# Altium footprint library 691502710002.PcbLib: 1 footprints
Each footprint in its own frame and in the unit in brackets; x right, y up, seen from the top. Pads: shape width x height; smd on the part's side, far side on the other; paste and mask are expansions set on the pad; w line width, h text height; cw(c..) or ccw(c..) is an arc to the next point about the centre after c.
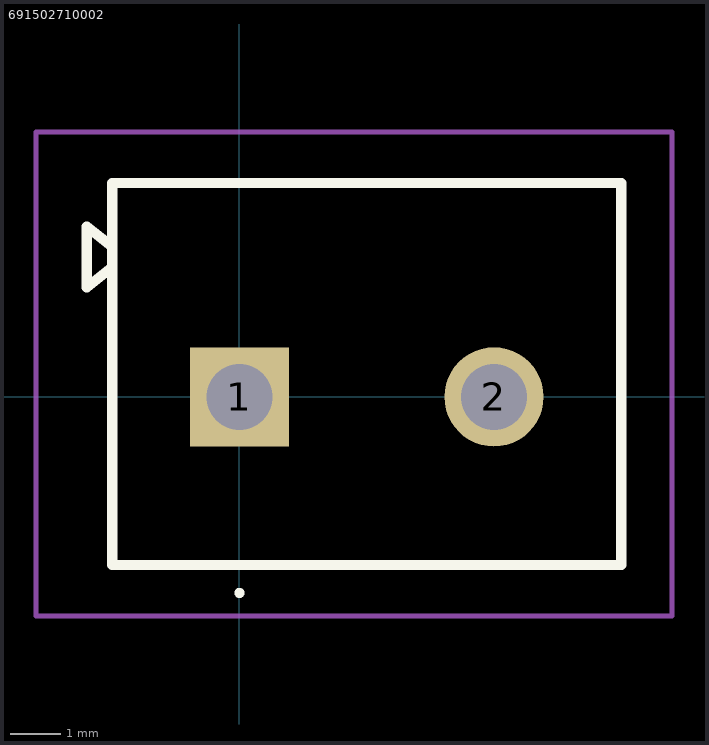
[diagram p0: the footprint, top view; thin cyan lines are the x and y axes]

## 691502710002 [mm]
pads (2):
  rect 1.95x1.95 hole 1.3: 1(0,0)
  round 1.95 hole 1.3: 2(5,0)
Top Overlay:
  lines w0.1: 0,-3.9 cw(c0,-3.85) 0,-3.8 ; 0,-3.9 0,-3.9 ; 0,-3.9 ccw(c0,-3.85) 0,-3.8 ; 0,-3.8 0,-3.8
  lines w0.2: -2.5,2.55 -3,2.15 -3,3.35 -2.5,2.95 ; -2.5,-3.3 7.5,-3.3 7.5,4.2 -2.5,4.2 -2.5,-3.3
Mechanical 15:
  lines w0.1: -2.5,2.55 -3,2.15 -3,3.35 -2.5,2.95 ; -2.5,-3.3 7.5,-3.3 7.5,4.2 -2.5,4.2 -2.5,-3.3
Mechanical 20:
  lines w0.1: -4,-4.3 8.5,-4.3 8.5,5.2 -4,5.2 -4,-4.3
